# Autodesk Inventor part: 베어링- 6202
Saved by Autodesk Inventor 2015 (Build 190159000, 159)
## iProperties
Created: 2025-08
Part Number: 베어링- 6202
Material: 일반
Document SubType Name: Modeling
Designer: user
Density: 1 g/cm^3
Appearance: 기본값
Author: jhkim
Description: 깊은 그루브 볼 베어링
Creation Date: 2025-08-05
Sending System: Autodesk Inventor 2026
Preprocessor: ST-DEVELOPER v20.1
Author: user
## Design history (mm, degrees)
node "베어링- 62021"
body "Solid1"
node "Solid1_1"
node "Solid1_2"
node "Solid1_3"
node "Solid1_4"
node "Solid1_5"
node "Solid1_6"
node "Solid1_7"
node "Solid1_8"
node "Solid1_9"
node "기준1"
node "기준2"
node "기준3"
node "기준4"
node "기준5"
node "기준6"
node "기준7"
node "기준8"
node "기준9"
node "기준10"
